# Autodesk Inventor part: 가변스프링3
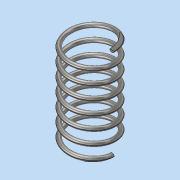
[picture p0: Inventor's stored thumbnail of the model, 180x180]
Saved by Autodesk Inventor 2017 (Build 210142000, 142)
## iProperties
Part Number: 가변스프링3
Material: 스테인레스 스틸
Document SubType Name: Modeling
Designer: MRC
Density: 8 g/cm^3
Appearance: 반연마
Mass: 10.9602 g
Surface Area: 27.6886 cm^2
Volume: 1.37003 cm^3
Author: MRC
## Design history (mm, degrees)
sketch "스케치1"
  geometry: L1 (0, 0)-(10, 0); L2 (10, 0)-(10, 41.411); L3 (10, 41.411)-(0, 41.411); L4 (0, 41.411)-(0, 0); C1 r 1 at (10, 0)
  constraints: 8 end point, 2 parallel, 1 centre point, 1 coincident, 1 horizontal, 1 perpendicular
  dimensions: "d0" = 20 diameter of L2 L4; "d1" = 41.4112 distance of L1.end L2.end (derived); "d2" = 2 diameter of C1
feature "코일1" sketch "스케치1" pitch "d3" = 10; turns "d5" = 7; dims "d4" = 41.4112 (= d1), "d6" = 0, angle "d7" = 90 deg, angle "d8" = 90 deg, "d9" = 0, "d10" = 0
sketch "스케치2"
  geometry: L1 (-15, 41.411)-(15, 41.411); L2 (15, 41.411)-(15, 0); L3 (15, 0)-(-15, 0); L4 (-15, 0)-(-15, 41.411); L5 (0, 41.411)-(0, 0) reference; 2 further points
  constraints: 8 end point, 2 midpoint, 2 parallel, 1 coincident, 1 horizontal, 1 perpendicular
  dimensions: "d11" = 30 distance of L1.start L1.end
extrude "돌출1" sketch "스케치2" stored distance "d12" = 0; taper "d13" = 0 deg
node "솔리드1"
